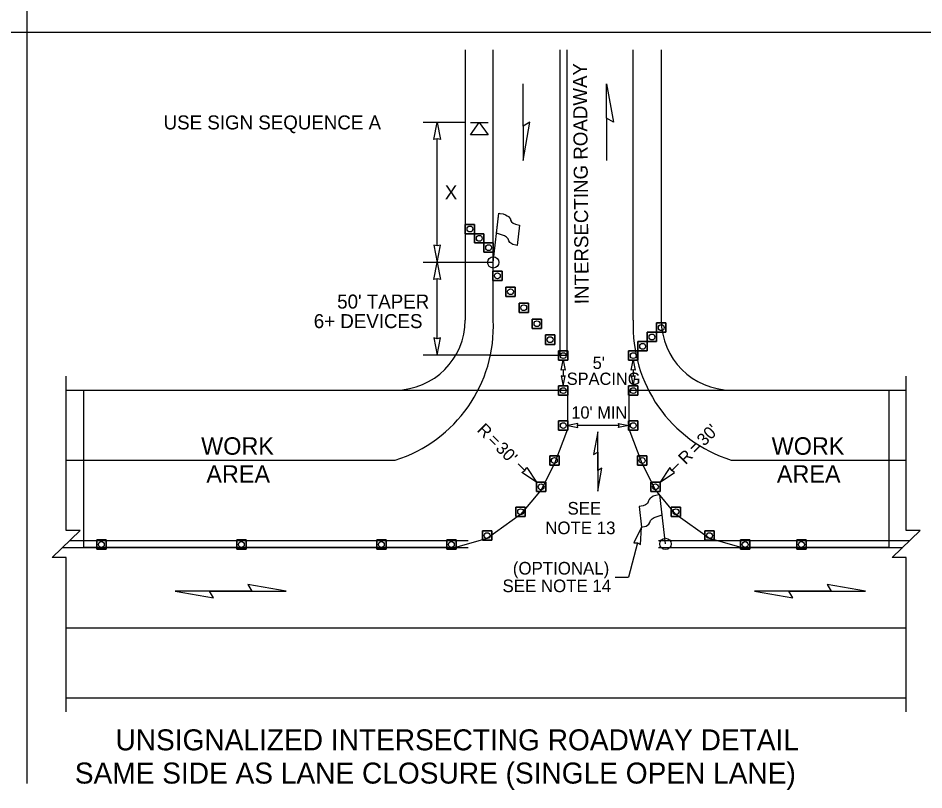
# Model space of a CAD drawing. Extents: x 99999.1 to 100095.7, y 99995 to 100010.7.
# Drawn here: x 100025.2 to 100030.38, y 100001.65 to 100006.06 of the extents above; entities that cross this region are included whole.
import ezdxf

# ---------------------------------------------------------------- set-up
doc = ezdxf.new("R2010")
doc.units = 0
for name, color, linetype in [('RD_ED_ShoulderPavedEdge', 7, 'Continuous'), ('RD_MK_LineDblYellowCenter', 7, 'Continuous'), ('RD_MK_LineEdgeWhite', 7, 'Continuous'), ('RD_MK_LineStop', 7, 'Continuous'), ('SH_DE_DetailBody1Text', 7, 'Continuous'), ('SH_DE_DetailHeading2Text', 7, 'Continuous'), ('TR_WZ_FlaggingStation', 7, 'Continuous'), ('TR_WZ_PortableSignMountBlk-Org', 7, 'Continuous'), ('TR_WZ_TrafficCone', 7, 'Continuous'), ('TR_WZ_WorkAreaLabel', 7, 'Continuous'), ('TR_WZ_WorkZoneDetails', 7, 'Continuous'), ('TR_WZ_WorkZoneTextCurrent', 7, 'Continuous')]:
    doc.layers.add(name, color=color, linetype=linetype)

msp = doc.modelspace()

# ---------------------------------------------------------------- linework, layer by layer
at = {"layer": 'RD_ED_ShoulderPavedEdge'}
for p, q in [((100025.475, 100003.9359), (100027.355, 100003.9359)), ((100029.275, 100003.9359), (100030.275, 100003.9359)), ((100025.475, 100002.1759), (100030.275, 100002.1759))]:
    msp.add_line(p, q, dxfattribs=at)
for points in [[(100027.755, 100005.8804), (100027.755, 100004.3359)], [(100028.875, 100005.8804), (100028.875, 100004.3359)]]:
    msp.add_lwpolyline(points, dxfattribs=at)
for centre, start, end in [((100027.355, 100004.3359), 270, 0), ((100029.275, 100004.3359), 180, 270)]:
    msp.add_arc(centre, 0.4, start, end, dxfattribs=at)
at = {"layer": 'RD_MK_LineDblYellowCenter'}
for p, q in [((100028.295, 100005.8804), (100028.295, 100004.1359)), ((100028.335, 100005.8804), (100028.335, 100004.1359)), ((100025.4957, 100003.0759), (100027.7712, 100003.0759)), ((100028.8588, 100003.0759), (100030.2957, 100003.0759)), ((100025.4543, 100003.0359), (100027.7712, 100003.0359)), ((100028.8588, 100003.0359), (100030.2543, 100003.0359))]:
    msp.add_line(p, q, dxfattribs=at)
at = {"layer": 'RD_MK_LineEdgeWhite'}
for p, q in [((100027.915, 100004.3359), (100027.915, 100005.8804)), ((100028.715, 100004.3359), (100028.715, 100005.8804)), ((100025.475, 100003.5359), (100027.355, 100003.5359)), ((100029.275, 100003.5359), (100030.275, 100003.5359)), ((100025.475, 100002.5759), (100030.275, 100002.5759))]:
    msp.add_line(p, q, dxfattribs=at)
for centre, start, end in [((100027.1158, 100004.2993), 287.3948, 2.6212), ((100029.5142, 100004.2993), 177.3788, 252.6052)]:
    msp.add_arc(centre, 0.8, start, end, dxfattribs=at)
at = {"layer": 'RD_MK_LineStop'}
msp.add_line((100027.899, 100004.1359), (100028.335, 100004.1359), dxfattribs=at)
at = {"layer": 'TR_WZ_FlaggingStation'}
for p, q in [((100027.915, 100004.6659), (100027.9471, 100004.9468)), ((100027.934, 100004.8328), (100027.9471, 100004.9471)), ((100028.065, 100004.8793), (100028.0517, 100004.7621)), ((100027.934, 100004.8328), (100027.934, 100004.8328)), ((100028.8797, 100003.2228), (100028.8667, 100003.3371)), ((100028.8988, 100003.0559), (100028.8667, 100003.3368)), ((100028.7487, 100003.2693), (100028.762, 100003.1521)), ((100028.8797, 100003.2228), (100028.8797, 100003.2228))]:
    msp.add_line(p, q, dxfattribs=at)
for points in [[(100027.9471, 100004.9471), (100027.9528, 100004.9459), (100027.9707, 100004.9424), (100027.9845, 100004.9383), (100027.9942, 100004.9322), (100028.0027, 100004.9275), (100028.0084, 100004.9206), (100028.0126, 100004.9128), (100028.0131, 100004.9066), (100028.0185, 100004.8974), (100028.0293, 100004.8899), (100028.0417, 100004.8847), (100028.065, 100004.8793)], [(100028.0517, 100004.7621), (100028.0436, 100004.7636), (100028.0259, 100004.7682), (100028.0103, 100004.7787), (100028.0037, 100004.7893), (100027.9998, 100004.7996), (100027.9907, 100004.8105), (100027.9798, 100004.8167), (100027.9624, 100004.8238), (100027.934, 100004.8328)], [(100028.8667, 100003.3371), (100028.8609, 100003.3359), (100028.8431, 100003.3324), (100028.8293, 100003.3283), (100028.8196, 100003.3222), (100028.8111, 100003.3175), (100028.8054, 100003.3106), (100028.8012, 100003.3028), (100028.8006, 100003.2966), (100028.7953, 100003.2874), (100028.7845, 100003.2799), (100028.7721, 100003.2747), (100028.7487, 100003.2693)], [(100028.762, 100003.1521), (100028.7702, 100003.1536), (100028.7879, 100003.1582), (100028.8035, 100003.1687), (100028.81, 100003.1793), (100028.814, 100003.1896), (100028.823, 100003.2005), (100028.834, 100003.2067), (100028.8514, 100003.2138), (100028.8797, 100003.2228)]]:
    msp.add_lwpolyline(points, dxfattribs=at)
for centre in [(100027.915, 100004.6659), (100028.8988, 100003.0559)]:
    msp.add_circle(centre, 0.0325, dxfattribs=at)
at = {"layer": 'TR_WZ_PortableSignMountBlk-Org'}
msp.add_line((100027.785, 100005.4659), (100027.885, 100005.4659), dxfattribs=at)
msp.add_lwpolyline([(100027.8349, 100005.4659), (100027.885, 100005.3941), (100027.785, 100005.3941)], close=True, dxfattribs=at)
at = {"layer": 'TR_WZ_TrafficCone'}
for points in [[(100027.8083, 100004.8833), (100027.8083, 100004.8299), (100027.755, 100004.8299), (100027.755, 100004.8833), (100027.8083, 100004.8833)], [(100027.755, 100004.8833), (100027.755, 100004.8299), (100027.8083, 100004.8299), (100027.8083, 100004.8833), (100027.755, 100004.8833)], [(100027.8617, 100004.8299), (100027.8617, 100004.7766), (100027.8083, 100004.7766), (100027.8083, 100004.8299), (100027.8617, 100004.8299)], [(100027.8083, 100004.8299), (100027.8083, 100004.7766), (100027.8617, 100004.7766), (100027.8617, 100004.8299), (100027.8083, 100004.8299)], [(100027.915, 100004.7766), (100027.915, 100004.7233), (100027.8617, 100004.7233), (100027.8617, 100004.7766), (100027.915, 100004.7766)], [(100027.8617, 100004.7766), (100027.8617, 100004.7233), (100027.915, 100004.7233), (100027.915, 100004.7766), (100027.8617, 100004.7766)], [(100027.9117, 100004.6159), (100027.965, 100004.6159), (100027.965, 100004.5626), (100027.9117, 100004.5626), (100027.9117, 100004.6159)], [(100027.9117, 100004.5626), (100027.965, 100004.5626), (100027.965, 100004.6159), (100027.9117, 100004.6159), (100027.9117, 100004.5626)], [(100027.987, 100004.5246), (100028.0404, 100004.5246), (100028.0404, 100004.4712), (100027.987, 100004.4712), (100027.987, 100004.5246)], [(100027.987, 100004.4712), (100028.0404, 100004.4712), (100028.0404, 100004.5246), (100027.987, 100004.5246), (100027.987, 100004.4712)], [(100028.0624, 100004.4332), (100028.1157, 100004.4332), (100028.1157, 100004.3799), (100028.0624, 100004.3799), (100028.0624, 100004.4332)], [(100028.0624, 100004.3799), (100028.1157, 100004.3799), (100028.1157, 100004.4332), (100028.0624, 100004.4332), (100028.0624, 100004.3799)], [(100028.1377, 100004.3419), (100028.191, 100004.3419), (100028.191, 100004.2886), (100028.1377, 100004.2886), (100028.1377, 100004.3419)], [(100028.1377, 100004.2886), (100028.191, 100004.2886), (100028.191, 100004.3419), (100028.1377, 100004.3419), (100028.1377, 100004.2886)], [(100028.9016, 100004.3192), (100028.8483, 100004.3192), (100028.8483, 100004.2659), (100028.9016, 100004.2659), (100028.9016, 100004.3192)], [(100028.9016, 100004.2659), (100028.8483, 100004.2659), (100028.8483, 100004.3192), (100028.9016, 100004.3192), (100028.9016, 100004.2659)], [(100028.213, 100004.2506), (100028.2664, 100004.2506), (100028.2664, 100004.1972), (100028.213, 100004.1972), (100028.213, 100004.2506)], [(100028.213, 100004.1972), (100028.2664, 100004.1972), (100028.2664, 100004.2506), (100028.213, 100004.2506), (100028.213, 100004.1972)], [(100028.8483, 100004.2659), (100028.795, 100004.2659), (100028.795, 100004.2126), (100028.8483, 100004.2126), (100028.8483, 100004.2659)], [(100028.8483, 100004.2126), (100028.795, 100004.2126), (100028.795, 100004.2659), (100028.8483, 100004.2659), (100028.8483, 100004.2126)], [(100028.795, 100004.2126), (100028.7416, 100004.2126), (100028.7416, 100004.1592), (100028.795, 100004.1592), (100028.795, 100004.2126)], [(100028.795, 100004.1592), (100028.7416, 100004.1592), (100028.7416, 100004.2126), (100028.795, 100004.2126), (100028.795, 100004.1592)], [(100028.2884, 100004.1592), (100028.3417, 100004.1592), (100028.3417, 100004.1059), (100028.2884, 100004.1059), (100028.2884, 100004.1592)], [(100028.2884, 100004.1059), (100028.3417, 100004.1059), (100028.3417, 100004.1592), (100028.2884, 100004.1592), (100028.2884, 100004.1059)], [(100028.7416, 100004.1592), (100028.6883, 100004.1592), (100028.6883, 100004.1059), (100028.7416, 100004.1059), (100028.7416, 100004.1592)], [(100028.7416, 100004.1059), (100028.6883, 100004.1059), (100028.6883, 100004.1592), (100028.7416, 100004.1592), (100028.7416, 100004.1059)], [(100028.2884, 100003.9592), (100028.3417, 100003.9592), (100028.3417, 100003.9059), (100028.2884, 100003.9059), (100028.2884, 100003.9592)], [(100028.2884, 100003.9059), (100028.3417, 100003.9059), (100028.3417, 100003.9592), (100028.2884, 100003.9592), (100028.2884, 100003.9059)], [(100028.7416, 100003.9592), (100028.6883, 100003.9592), (100028.6883, 100003.9059), (100028.7416, 100003.9059), (100028.7416, 100003.9592)], [(100028.7416, 100003.9059), (100028.6883, 100003.9059), (100028.6883, 100003.9592), (100028.7416, 100003.9592), (100028.7416, 100003.9059)], [(100028.2884, 100003.7592), (100028.3417, 100003.7592), (100028.3417, 100003.7059), (100028.2884, 100003.7059), (100028.2884, 100003.7592)], [(100028.2884, 100003.7059), (100028.3417, 100003.7059), (100028.3417, 100003.7592), (100028.2884, 100003.7592), (100028.2884, 100003.7059)], [(100028.7416, 100003.7592), (100028.6883, 100003.7592), (100028.6883, 100003.7059), (100028.7416, 100003.7059), (100028.7416, 100003.7592)], [(100028.7416, 100003.7059), (100028.6883, 100003.7059), (100028.6883, 100003.7592), (100028.7416, 100003.7592), (100028.7416, 100003.7059)], [(100028.2373, 100003.5592), (100028.2907, 100003.5592), (100028.2907, 100003.5059), (100028.2373, 100003.5059), (100028.2373, 100003.5592)], [(100028.2373, 100003.5059), (100028.2907, 100003.5059), (100028.2907, 100003.5592), (100028.2373, 100003.5592), (100028.2373, 100003.5059)], [(100028.7927, 100003.5592), (100028.7393, 100003.5592), (100028.7393, 100003.5059), (100028.7927, 100003.5059), (100028.7927, 100003.5592)], [(100028.7927, 100003.5059), (100028.7393, 100003.5059), (100028.7393, 100003.5592), (100028.7927, 100003.5592), (100028.7927, 100003.5059)], [(100028.1617, 100003.4093), (100028.215, 100003.4093), (100028.215, 100003.3559), (100028.1617, 100003.3559), (100028.1617, 100003.4093)], [(100028.1617, 100003.3559), (100028.215, 100003.3559), (100028.215, 100003.4093), (100028.1617, 100003.4093), (100028.1617, 100003.3559)], [(100028.8683, 100003.4093), (100028.815, 100003.4093), (100028.815, 100003.3559), (100028.8683, 100003.3559), (100028.8683, 100003.4093)], [(100028.8683, 100003.3559), (100028.815, 100003.3559), (100028.815, 100003.4093), (100028.8683, 100003.4093), (100028.8683, 100003.3559)], [(100028.0447, 100003.267), (100028.0981, 100003.267), (100028.0981, 100003.2136), (100028.0447, 100003.2136), (100028.0447, 100003.267)], [(100028.0447, 100003.2136), (100028.0981, 100003.2136), (100028.0981, 100003.267), (100028.0447, 100003.267), (100028.0447, 100003.2136)], [(100028.9853, 100003.267), (100028.9319, 100003.267), (100028.9319, 100003.2136), (100028.9853, 100003.2136), (100028.9853, 100003.267)], [(100028.9853, 100003.2136), (100028.9319, 100003.2136), (100028.9319, 100003.267), (100028.9853, 100003.267), (100028.9853, 100003.2136)], [(100027.853, 100003.1302), (100027.9064, 100003.1302), (100027.9064, 100003.0768), (100027.853, 100003.0768), (100027.853, 100003.1302)], [(100027.853, 100003.0768), (100027.9064, 100003.0768), (100027.9064, 100003.1302), (100027.853, 100003.1302), (100027.853, 100003.0768)], [(100029.177, 100003.1302), (100029.1236, 100003.1302), (100029.1236, 100003.0768), (100029.177, 100003.0768), (100029.177, 100003.1302)], [(100029.177, 100003.0768), (100029.1236, 100003.0768), (100029.1236, 100003.1302), (100029.177, 100003.1302), (100029.177, 100003.0768)], [(100025.649, 100003.0792), (100025.7024, 100003.0792), (100025.7024, 100003.0259), (100025.649, 100003.0259), (100025.649, 100003.0792)], [(100025.649, 100003.0259), (100025.7024, 100003.0259), (100025.7024, 100003.0792), (100025.649, 100003.0792), (100025.649, 100003.0259)], [(100026.449, 100003.0792), (100026.5024, 100003.0792), (100026.5024, 100003.0259), (100026.449, 100003.0259), (100026.449, 100003.0792)], [(100026.449, 100003.0259), (100026.5024, 100003.0259), (100026.5024, 100003.0792), (100026.449, 100003.0792), (100026.449, 100003.0259)], [(100027.249, 100003.0792), (100027.3024, 100003.0792), (100027.3024, 100003.0259), (100027.249, 100003.0259), (100027.249, 100003.0792)], [(100027.249, 100003.0259), (100027.3024, 100003.0259), (100027.3024, 100003.0792), (100027.249, 100003.0792), (100027.249, 100003.0259)], [(100027.649, 100003.0792), (100027.7024, 100003.0792), (100027.7024, 100003.0259), (100027.649, 100003.0259), (100027.649, 100003.0792)], [(100027.649, 100003.0259), (100027.7024, 100003.0259), (100027.7024, 100003.0792), (100027.649, 100003.0792), (100027.649, 100003.0259)], [(100029.381, 100003.0792), (100029.3276, 100003.0792), (100029.3276, 100003.0259), (100029.381, 100003.0259), (100029.381, 100003.0792)], [(100029.381, 100003.0259), (100029.3276, 100003.0259), (100029.3276, 100003.0792), (100029.381, 100003.0792), (100029.381, 100003.0259)], [(100029.649, 100003.0792), (100029.7024, 100003.0792), (100029.7024, 100003.0259), (100029.649, 100003.0259), (100029.649, 100003.0792)], [(100029.649, 100003.0259), (100029.7024, 100003.0259), (100029.7024, 100003.0792), (100029.649, 100003.0792), (100029.649, 100003.0259)]]:
    msp.add_lwpolyline(points, dxfattribs=at)
for centre in [(100027.7817, 100004.8566), (100027.835, 100004.8033), (100027.8883, 100004.7499), (100027.9384, 100004.5892), (100028.0137, 100004.4979), (100028.089, 100004.4066), (100028.1644, 100004.3152), (100028.875, 100004.2926), (100028.8216, 100004.2392), (100028.2397, 100004.2239), (100028.7683, 100004.1859), (100028.315, 100004.1326), (100028.715, 100004.1326), (100028.315, 100003.9326), (100028.715, 100003.9326), (100028.315, 100003.7326), (100028.715, 100003.7326), (100028.264, 100003.5326), (100028.766, 100003.5326), (100028.1883, 100003.3826), (100028.8417, 100003.3826), (100028.0714, 100003.2403), (100028.9586, 100003.2403), (100027.8797, 100003.1035), (100029.1503, 100003.1035), (100025.6757, 100003.0526), (100026.4757, 100003.0526), (100027.2757, 100003.0526), (100027.6757, 100003.0526), (100029.3543, 100003.0526), (100029.6757, 100003.0526)]:
    msp.add_circle(centre, 0.0167, dxfattribs=at)
at = {"layer": 'TR_WZ_WorkZoneDetails'}
for p, q in [((100025.25, 100010.275), (100025.25, 100001.6859)), ((100025.25, 100005.9804), (100020, 100005.9804)), ((100030.5, 100005.9804), (100025.25, 100005.9804)), ((100028.0855, 100005.4448), (100028.0855, 100005.6859)), ((100027.755, 100005.4659), (100027.515, 100005.4659)), ((100028.5627, 100005.4894), (100028.5627, 100005.2483)), ((100027.595, 100004.7596), (100027.595, 100005.3722)), ((100027.915, 100004.6659), (100027.515, 100004.6659)), ((100027.595, 100004.2296), (100027.595, 100004.5722)), ((100027.899, 100004.1359), (100027.515, 100004.1359)), ((100028.315, 100004.0514), (100028.315, 100004.0137)), ((100028.715, 100004.0514), (100028.715, 100004.0137)), ((100028.6338, 100003.7326), (100028.3962, 100003.7326)), ((100028.5115, 100003.4752), (100028.5115, 100003.6199)), ((100028.5115, 100003.5799), (100028.5115, 100003.4352)), ((100028.0954, 100003.4755), (100028.057, 100003.514)), ((100028.9346, 100003.4755), (100028.973, 100003.514)), ((100028.7385, 100003.0614), (100028.688, 100002.8668)), ((100028.6118, 100002.8668), (100028.688, 100002.8668)), ((100026.2944, 100002.7859), (100026.5356, 100002.7859)), ((100026.5356, 100002.7859), (100026.2944, 100002.7859)), ((100029.6043, 100002.7859), (100029.8454, 100002.7859)), ((100029.8454, 100002.7859), (100029.6043, 100002.7859))]:
    msp.add_line(p, q, dxfattribs=at)
for points in [[(100028.5627, 100005.6859), (100028.6013, 100005.4671), (100028.5627, 100005.4894)], [(100027.595, 100005.4659), (100027.6143, 100005.3676), (100027.595, 100005.3722), (100027.5757, 100005.3676)], [(100028.0855, 100005.2483), (100028.124, 100005.4671), (100028.0855, 100005.4448)], [(100027.595, 100004.6659), (100027.6143, 100004.7642), (100027.595, 100004.7596), (100027.5757, 100004.7642)], [(100027.595, 100004.6659), (100027.6143, 100004.5676), (100027.595, 100004.5722), (100027.5757, 100004.5676)], [(100027.595, 100004.1359), (100027.6143, 100004.2342), (100027.595, 100004.2296), (100027.5757, 100004.2342)], [(100028.315, 100004.1059), (100028.3262, 100004.0487), (100028.315, 100004.0514), (100028.3038, 100004.0487)], [(100028.7149, 100004.1059), (100028.7261, 100004.0487), (100028.7149, 100004.0514), (100028.7037, 100004.0487)], [(100028.315, 100003.9592), (100028.3263, 100004.0164), (100028.315, 100004.0137), (100028.3038, 100004.0164)], [(100028.715, 100003.9592), (100028.7262, 100004.0164), (100028.715, 100004.0137), (100028.7037, 100004.0164)], [(100028.3383, 100003.9359), (100028.3383, 100003.7126), (100028.264, 100003.5159), (100028.1883, 100003.3659), (100028.1883, 100003.3659), (100028.1883, 100003.3659), (100028.0714, 100003.2236), (100028.0714, 100003.2236), (100028.0714, 100003.2236), (100027.8797, 100003.0868), (100027.699, 100003.0359), (100026.499, 100003.0359), (100025.699, 100003.0359), (100025.575, 100003.0359), (100025.575, 100003.9359)], [(100030.175, 100003.9359), (100030.175, 100003.0359), (100029.699, 100003.0359), (100029.6523, 100003.0359), (100029.6523, 100003.0359), (100029.6523, 100003.0359), (100029.331, 100003.0359), (100029.331, 100003.0359), (100029.331, 100003.0359), (100029.1503, 100003.0868), (100028.9586, 100003.2236), (100028.8417, 100003.3659), (100028.766, 100003.5159), (100028.6917, 100003.7126), (100028.6917, 100003.9359)], [(100028.3417, 100003.7326), (100028.3989, 100003.7214), (100028.3962, 100003.7326), (100028.3989, 100003.7438)], [(100028.6883, 100003.7326), (100028.6311, 100003.7214), (100028.6338, 100003.7326), (100028.6311, 100003.7438)], [(100028.5115, 100003.6978), (100028.4883, 100003.5665), (100028.5115, 100003.5799)], [(100028.1617, 100003.4093), (100028.0786, 100003.4652), (100028.0954, 100003.4756), (100028.1058, 100003.4924)], [(100028.5115, 100003.3573), (100028.5346, 100003.4886), (100028.5115, 100003.4752)], [(100028.8683, 100003.4093), (100028.9514, 100003.4652), (100028.9346, 100003.4756), (100028.9242, 100003.4924)], [(100028.762, 100003.1521), (100028.7187, 100003.0618), (100028.7385, 100003.0614), (100028.7561, 100003.0522)], [(100026.7321, 100002.7859), (100026.5133, 100002.8245), (100026.5356, 100002.7859)], [(100030.0419, 100002.7859), (100029.8231, 100002.8245), (100029.8454, 100002.7859)], [(100026.0979, 100002.7859), (100026.3167, 100002.7473), (100026.2944, 100002.7859)], [(100029.4077, 100002.7859), (100029.6265, 100002.7473), (100029.6043, 100002.7859)]]:
    msp.add_lwpolyline(points, close=True, dxfattribs=at)
for points in [[(100025.475, 100002.0959), (100025.475, 100002.9785), (100025.395, 100002.9785), (100025.555, 100003.1333), (100025.475, 100003.1333), (100025.475, 100004.0159)], [(100030.275, 100002.0959), (100030.275, 100002.9785), (100030.195, 100002.9785), (100030.355, 100003.1333), (100030.275, 100003.1333), (100030.275, 100004.0159)]]:
    msp.add_lwpolyline(points, dxfattribs=at)

# ---------------------------------------------------------------- texts
at = {"layer": 'SH_DE_DetailBody1Text'}
msp.add_text('INTERSECTING ROADWAY', height=0.08, rotation=90.4626, dxfattribs=at).set_placement((100028.4607, 100004.4269))
at = {"layer": 'SH_DE_DetailHeading2Text'}
for s, p in [('UNSIGNALIZED INTERSECTING ROADWAY DETAIL', (100025.7563, 100001.8759)), ('SAME SIDE AS LANE CLOSURE (SINGLE OPEN LANE)', (100025.524, 100001.6859))]:
    msp.add_text(s, height=0.12, rotation=360, dxfattribs=at).set_placement(p)
at = {"layer": 'TR_WZ_WorkAreaLabel'}
for s, p in [('WORK', (100026.2458, 100003.5659)), ('WORK', (100029.5056, 100003.5659)), ('AREA', (100026.2754, 100003.4059)), ('AREA', (100029.5352, 100003.4059))]:
    msp.add_text(s, height=0.1, dxfattribs=at).set_placement(p)
at = {"layer": 'TR_WZ_WorkZoneTextCurrent'}
for s, height, p in [('USE SIGN SEQUENCE A', 0.08, (100026.0313, 100005.4259)), ('X', 0.08, (100027.6379, 100005.0259)), ("50' TAPER", 0.08, (100027.0232, 100004.4019)), ('6+ DEVICES', 0.08, (100026.8892, 100004.2899)), ("5'", 0.07, (100028.483, 100004.0564)), ('SPACING', 0.07, (100028.3346, 100003.9654)), ("10' MIN", 0.07, (100028.3608, 100003.7726)), ('SEE', 0.072, (100028.3391, 100003.2239)), ('NOTE 13', 0.072, (100028.2119, 100003.1119)), ('(OPTIONAL)', 0.072, (100028.0267, 100002.8812)), ('SEE NOTE 14', 0.072, (100027.9678, 100002.7804))]:
    msp.add_text(s, height=height, dxfattribs=at).set_placement(p)
for s, rotation, p in [('R', 315, (100027.8182, 100003.7032)), ("30'", 45, (100029.1202, 100003.6116)), ('=', 315, (100027.8774, 100003.644)), ("30'", 315, (100027.9242, 100003.5972)), ('=', 45, (100029.0734, 100003.5648)), ('R', 45, (100029.0142, 100003.5056))]:
    msp.add_text(s, height=0.07, rotation=rotation, dxfattribs=at).set_placement(p)

doc.saveas('drawing.dxf')
